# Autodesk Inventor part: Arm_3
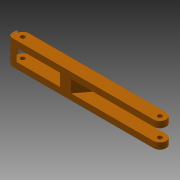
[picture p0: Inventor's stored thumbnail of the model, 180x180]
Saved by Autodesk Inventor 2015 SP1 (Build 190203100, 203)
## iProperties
Created: 2008-11
Part Number: Arm_3
Document SubType Name: Modeling
Designer: dwoollam
Density: 7.85 g/cm^3
Material: Steel
Appearance: Orange
Mass: 277737 g
Surface Area: 15687.7 cm^2
Volume: 35380.5 cm^3
Dwg_Category: Clearance_Mewp
INSTALLATION: False
CIVIL_WORK: False
EARTHING: False
MOUNTING: False
Author: dwoollam
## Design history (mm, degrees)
sketch "Sketch1" dims "d41" = 1202, "d42" = 993, "d45" = 85
  geometry: L1 (0, 70)-(1550, 70); L2 (0, -70)-(1550, -70); L3 (596.91, 70)-(491.541, -70); L4 (722.068, 70)-(616.699, -70); L5 (0, -70)-(-50, -70); L6 (-100, -20)-(-100, 20.019); L7 (-31.209, -28.849)-(-82.657, 26.807); L8 (0, 0)-(0, 70); C1 r 25 at (0, 0); C2 r 25 at (1550, 0); A1 r 70 centre (0, 0) between (0, 70) and (0, -70); A2 r 70 centre (1550, 0) between (1550, -70) and (1550, 70); A3 r 50 centre (-50, -20) between (-100, -20) and (-50, -70); A4 r 10 centre (-90, 20.019) between (-82.657, 26.807) and (-100, 20.019); 5 further points
  constraints: 16 end point, 10 point on circle, 9 tangent, 7 point on line, 6 centre point, 6 coincident, 2 parallel, 1 collinear, 1 equal radius, 1 horizontal, 1 perpendicular, 10 other
  dimensions: "d38" = 50 diameter of C1; "d39" = 140 diameter of A1; "d40" = 1550 distance of C2.centre point (0, 0); "d43" = 100 distance between parallel lines of L4 L3; "d47" = 50 radius of A3; "d48" = 100 horizontal distance of point (0, 0) L6.start; "d49" = 10 radius of A4; "d50" = 42.75 deg angle of L8 L7
extrude "Main_Body" new body sketch "Sketch1" stored distance "d24" = 280; taper "d25" = 0 deg
extrude "Main_Body_Sub" cut sketch "Sketch1" stored distance "d26" = 140; taper "d27" = 0 deg
extrude "Main_Body_2" join sketch "Sketch1" stored distance "d34" = 140; taper "d35" = 0 deg
body "Solid1"
